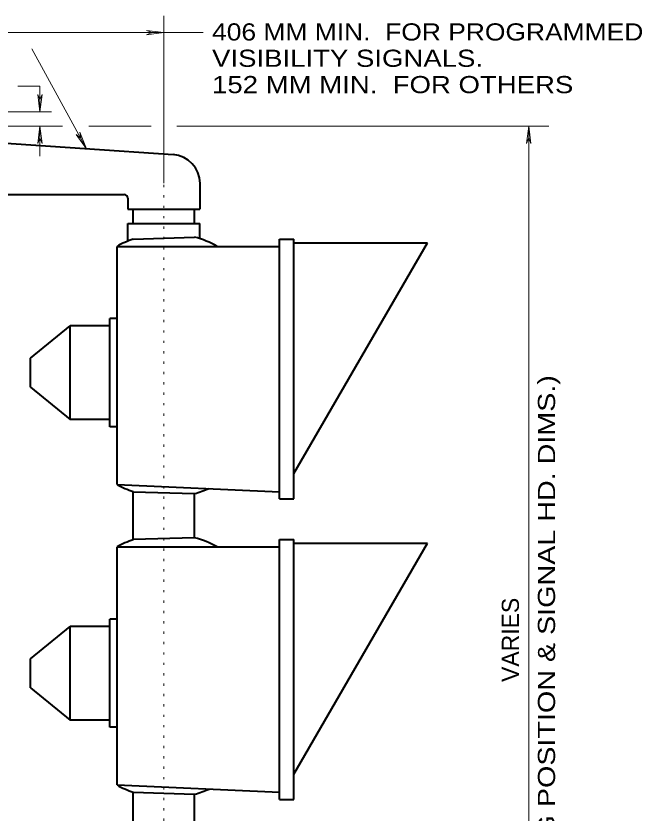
# Model space of a CAD drawing. Extents: x 312583 to 312854, y 144419 to 144597.
# Drawn here: x 312744.93 to 312772.65, y 144479.26 to 144514.56 of the extents above; entities that cross this region are included whole.
import ezdxf

# ---------------------------------------------------------------- set-up
doc = ezdxf.new("R2010")
doc.units = 0
doc.header["$LTSCALE"] = 0.3
doc.linetypes.add('DOTTED', pattern=[1.5, 0.3, -1.2])
doc.layers.add('1', color=7, linetype='Continuous', lineweight=40)
doc.layers.add('2', color=7, linetype='Continuous', lineweight=40)

msp = doc.modelspace()

# ---------------------------------------------------------------- linework, layer by layer
at = {"layer": '1'}
for p, q in [((312742.8551, 144509.0419), (312751.8864, 144508.4209)), ((312753.0748, 144507.1482), (312753.0748, 144506.0059)), ((312742.8551, 144506.6499), (312749.7244, 144506.6499)), ((312749.8854, 144506.4889), (312749.8854, 144506.0059)), ((312749.8854, 144506.0059), (312753.0748, 144506.0059)), ((312750.1231, 144505.3695), (312750.1231, 144506.0059)), ((312752.8371, 144505.3695), (312752.8371, 144506.0059)), ((312749.8854, 144505.3695), (312753.0748, 144505.3695)), ((312749.8854, 144504.5875), (312749.8854, 144505.3695)), ((312753.0748, 144504.6949), (312753.0748, 144505.3695)), ((312750.1231, 144504.6795), (312752.8371, 144504.7639)), ((312756.5938, 144493.1795), (312756.5938, 144504.6795)), ((312756.5938, 144504.6795), (312757.2301, 144504.6795)), ((312757.2301, 144493.1795), (312757.2301, 144504.6795)), ((312749.4024, 144504.3575), (312756.5938, 144504.3575)), ((312749.4024, 144493.8159), (312749.4024, 144504.3575)), ((312757.2301, 144504.5185), (312763.1411, 144504.5185)), ((312757.2301, 144494.2989), (312763.1411, 144504.5185)), ((312749.0881, 144496.3689), (312749.0881, 144501.1605)), ((312749.4024, 144501.1605), (312749.0881, 144501.1605)), ((312745.5691, 144499.4049), (312747.3248, 144500.8385)), ((312747.3248, 144496.6909), (312747.3248, 144500.8385)), ((312749.0881, 144500.8385), (312747.3248, 144500.8385)), ((312745.5691, 144498.1245), (312745.5691, 144499.4049)), ((312745.5691, 144498.1245), (312747.3248, 144496.6909)), ((312749.0881, 144496.6909), (312747.3248, 144496.6909)), ((312749.4024, 144496.3689), (312749.0881, 144496.3689)), ((312749.4024, 144493.8159), (312756.5938, 144493.4939)), ((312750.1231, 144491.3702), (312750.1231, 144493.4939)), ((312750.1231, 144493.4939), (312752.8371, 144493.4095)), ((312752.8371, 144491.4545), (312752.8371, 144493.4095)), ((312756.5938, 144493.1795), (312757.2301, 144493.1795)), ((312752.8371, 144491.4545), (312750.1231, 144491.3702)), ((312756.5938, 144479.8702), (312756.5938, 144491.3702)), ((312756.5938, 144491.3702), (312757.2301, 144491.3702)), ((312757.2301, 144479.8702), (312757.2301, 144491.3702)), ((312757.2301, 144491.2092), (312763.1411, 144491.2092)), ((312757.2301, 144480.9819), (312763.1411, 144491.2092)), ((312749.4024, 144491.0482), (312756.5938, 144491.0482)), ((312749.4024, 144480.5065), (312749.4024, 144491.0482)), ((312749.0881, 144483.0595), (312749.0881, 144487.8512)), ((312749.4024, 144487.8512), (312749.0881, 144487.8512)), ((312745.5691, 144486.0955), (312747.3248, 144487.5292)), ((312747.3248, 144483.3815), (312747.3248, 144487.5292)), ((312749.0881, 144487.5292), (312747.3248, 144487.5292)), ((312745.5691, 144484.8152), (312745.5691, 144486.0955)), ((312745.5691, 144484.8152), (312747.3248, 144483.3815)), ((312749.0881, 144483.3815), (312747.3248, 144483.3815)), ((312749.4024, 144483.0595), (312749.0881, 144483.0595)), ((312749.4024, 144480.5065), (312756.5938, 144480.1845)), ((312750.1231, 144478.0609), (312750.1231, 144480.1845)), ((312750.1231, 144480.1845), (312752.8371, 144480.1002)), ((312752.8371, 144478.1452), (312752.8371, 144480.1002)), ((312756.5938, 144479.8702), (312757.2301, 144479.8702))]:
    msp.add_line(p, q, dxfattribs=at)
at = {"layer": '1', "linetype": 'DOTTED', "lineweight": 13}
msp.add_line((312751.4801, 144465.1195), (312751.4801, 144507.1559), dxfattribs=at)
at = {"layer": '1'}
for centre, radius, start, end in [((312751.7995, 144507.1458), 1.2778, 0, 86.05287), ((312749.7232, 144506.4882), 0.1597, 0, 90), ((312751.6219, 144500.3546), 4.5776, 109.12156, 118.98507), ((312751.6219, 144500.3546), 4.5776, 61.01507, 74.59737), ((312751.6219, 144497.8214), 4.5776, 241.01493, 250.87844), ((312751.6219, 144497.8214), 4.5776, 285.40263, 293.90144), ((312751.6219, 144487.0439), 4.5776, 109.12156, 118.98507), ((312751.6219, 144487.0439), 4.5776, 61.01507, 74.59737), ((312751.6219, 144484.5108), 4.5776, 241.01493, 250.87844), ((312751.6219, 144484.5108), 4.5776, 285.40263, 293.90144)]:
    msp.add_arc(centre, radius, start, end, dxfattribs=at)
at = {"layer": '2', "lineweight": 13}
for p, q in [((312751.4801, 144507.1559), (312751.4801, 144514.5619)), ((312741.0994, 144513.8259), (312753.2204, 144513.8259)), ((312750.7134, 144513.9179), (312750.9588, 144513.8259)), ((312751.4801, 144513.8259), (312750.7134, 144513.9179)), ((312750.7134, 144513.7262), (312750.9588, 144513.8259)), ((312751.4801, 144513.8259), (312750.7134, 144513.7262)), ((312748.0454, 144508.6815), (312745.6381, 144513.1052)), ((312745.9908, 144511.4569), (312745.0094, 144511.4569)), ((312745.9908, 144510.3222), (312745.9908, 144511.4569)), ((312745.8988, 144511.0889), (312745.9908, 144510.8435)), ((312745.9908, 144510.3222), (312745.8988, 144511.0889)), ((312746.0828, 144511.0889), (312745.9908, 144510.8435)), ((312745.9908, 144510.3222), (312746.0828, 144511.0889)), ((312742.7861, 144510.3222), (312746.5044, 144510.3222)), ((312743.4991, 144509.6859), (312746.9874, 144509.6859)), ((312745.9908, 144509.6859), (312745.8988, 144508.9115)), ((312745.9908, 144508.3595), (312745.9908, 144509.6859)), ((312745.9908, 144509.6859), (312746.0828, 144508.9115)), ((312748.1604, 144509.6859), (312750.9128, 144509.6859)), ((312752.0551, 144509.6859), (312768.5231, 144509.6859)), ((312767.6261, 144509.6859), (312767.5264, 144508.9115)), ((312767.6261, 144462.4055), (312767.6261, 144509.6859)), ((312767.6261, 144509.6859), (312767.7181, 144508.9115)), ((312747.5931, 144509.3179), (312747.8001, 144509.1492)), ((312748.0454, 144508.6815), (312747.5931, 144509.3179)), ((312747.7618, 144509.4099), (312747.8001, 144509.1492)), ((312748.0454, 144508.6815), (312747.7618, 144509.4099)), ((312745.8988, 144508.9115), (312745.9908, 144509.1569)), ((312746.0828, 144508.9115), (312745.9908, 144509.1569)), ((312767.5264, 144508.9115), (312767.6261, 144509.1569)), ((312767.7181, 144508.9115), (312767.6261, 144509.1569))]:
    msp.add_line(p, q, dxfattribs=at)

# ---------------------------------------------------------------- texts
at = {"layer": '2'}
for s, width, p in [('406 MM MIN.  FOR PROGRAMMED', 1.15, (312753.6103, 144513.4746)), ('VISIBILITY SIGNALS.', 1.2, (312753.6103, 144512.3083)), ('152 MM MIN.  FOR OTHERS', 1.2, (312753.6103, 144511.142))]:
    msp.add_text(s, height=0.76, dxfattribs=dict(at, width=width)).set_placement(p)
at = {"layer": '2', "width": 1.25}
msp.add_text('(TO FIT MTG POSITION & SIGNAL HD. DIMS.)', height=0.76, rotation=90, dxfattribs=at).set_placement((312768.7951, 144471.553))
at = {"layer": '2'}
msp.add_text('VARIES', height=0.76, rotation=90, dxfattribs=at).set_placement((312767.1947, 144485.0691))

doc.saveas('drawing.dxf')
